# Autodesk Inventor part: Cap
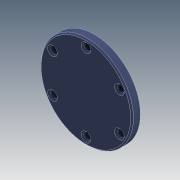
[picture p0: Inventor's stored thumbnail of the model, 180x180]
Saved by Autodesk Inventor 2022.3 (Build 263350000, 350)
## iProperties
Created: 2023-08
Part Number: Cap
Material: Generic
Document SubType Name: Modeling
Designer: irinventor.com
Density: 1 g/cm^3
Appearance: Default(2)
Author: irinventor.com
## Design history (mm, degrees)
sketch "Sketch1"
  geometry: C1 r 33.5 at (0, 0); 1 further point
  constraints: 1 centre point, 1 coincident
  dimensions: "d0" = 67 diameter of C1
extrude "Extrusion1" new body sketch "Sketch1" distance "d1" = 6; taper "d2" = 0 deg
sketch "Sketch2"
  geometry: 2 further points
  constraints: 1 vertical alignment
  dimensions: "d10" = 28 distance of point (0, 0) point (0, 28)
hole "Hole1" sketch "Sketch2" at (0, 28) diameter "d3" = 5; stored, may be unused: countersink angle "d7" = 90 deg, drill point angle "d9" = 118 deg; dims "d4" = 10, "d5" = 7, "d6" = 2, "d8" = 8
pattern_circular "Circular Pattern1" dims angle "d12" = 360 deg
chamfer "Chamfer1" distance "d14" = 1; stored, may be unused: second distance "d15" = 2, angle "d16" = 45 deg
body "Solid1"
